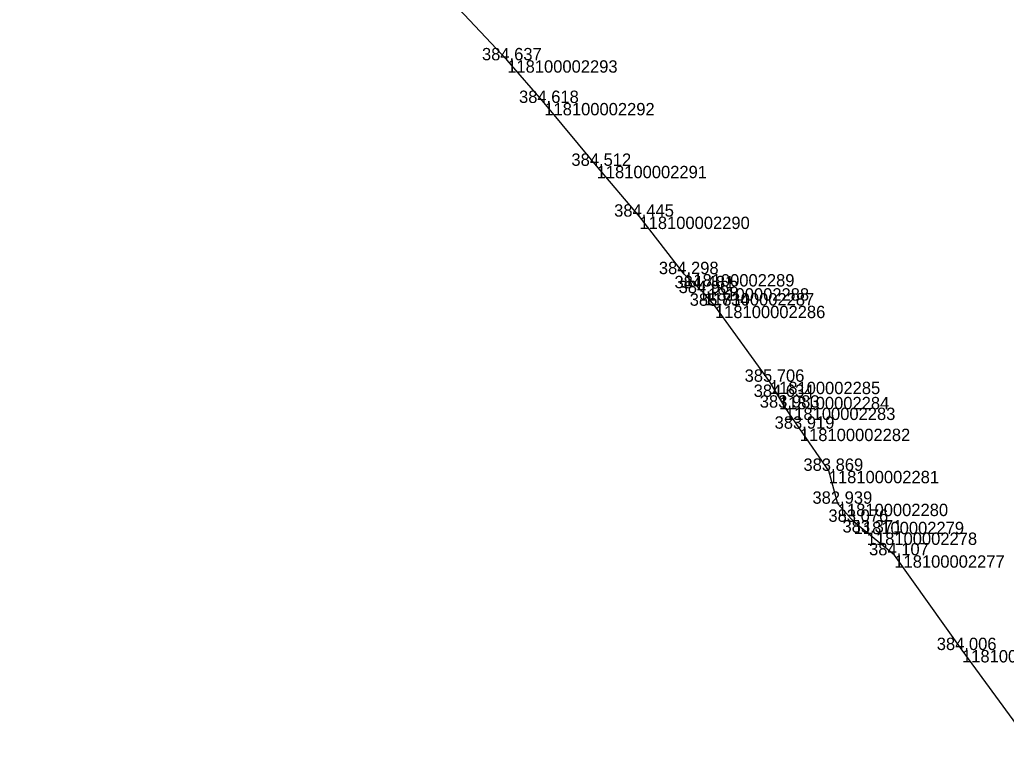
# Model space of a CAD drawing. Extents: x -724084 to -720954, y -948423 to -945131.
# Drawn here: x -721513.9 to -721418.2, y -948012.4 to -947941.8 of the extents above; entities that cross this region are included whole.
import ezdxf

# ---------------------------------------------------------------- set-up
doc = ezdxf.new("R2010")
doc.units = 0
for name, color, linetype in [('Vrstva 28', 7, 'Continuous'), ('Vrstva 31', 7, 'Continuous'), ('Vrstva 33', 7, 'Continuous'), ('Vrstva 60', 7, 'Continuous'), ('Vrstva 61', 7, 'Continuous')]:
    doc.layers.add(name, color=color, linetype=linetype)

msp = doc.modelspace()

# ---------------------------------------------------------------- linework, layer by layer
at = {"layer": 'Vrstva 28'}
for points in [[(-721448.033, -947967.826), (-721449.454, -947966.459), (-721453.791, -947960.883), (-721457.946, -947955.954), (-721463.023, -947949.853), (-721466.622, -947945.714), (-721471.841, -947940.171), (-721476.024, -947936.004), (-721481.396, -947930.254), (-721486.364, -947925.652), (-721492.33, -947920.175), (-721498.065, -947914.804), (-721503.374, -947910.249), (-721507.766, -947906.168), (-721509.45, -947905.616), (-721512.086, -947903.222), (-721513.94, -947901.829)], [(-721439.659, -947979.413), (-721440.252, -947978.369), (-721441.131, -947976.901), (-721446.462, -947969.527), (-721447.536, -947968.302), (-721448.033, -947967.826)], [(-721415.562, -948012.362), (-721422.481, -948002.931), (-721429.051, -947993.74), (-721431.726, -947991.529), (-721432.996, -947990.487), (-721434.542, -947988.736), (-721435.418, -947985.544), (-721438.218, -947981.456), (-721439.659, -947979.413)]]:
    msp.add_lwpolyline(points, dxfattribs=at)
at = {"layer": 'Vrstva 31'}
for points in [[(-721448.033, -947967.826), (-721449.454, -947966.459), (-721453.791, -947960.883), (-721457.946, -947955.954), (-721463.023, -947949.853), (-721466.622, -947945.714), (-721471.841, -947940.171), (-721476.024, -947936.004), (-721481.396, -947930.254), (-721486.364, -947925.652), (-721492.33, -947920.175), (-721498.065, -947914.804), (-721503.374, -947910.249), (-721507.766, -947906.168), (-721509.45, -947905.616), (-721512.086, -947903.222), (-721513.94, -947901.829)], [(-721439.659, -947979.413), (-721440.252, -947978.369), (-721441.131, -947976.901), (-721446.462, -947969.527), (-721447.536, -947968.302), (-721448.033, -947967.826)], [(-721415.562, -948012.362), (-721422.481, -948002.931), (-721429.051, -947993.74), (-721431.726, -947991.529), (-721432.996, -947990.487), (-721434.542, -947988.736), (-721435.418, -947985.544), (-721438.218, -947981.456), (-721439.659, -947979.413)]]:
    msp.add_lwpolyline(points, dxfattribs=at)
at = {"layer": 'Vrstva 33'}
msp.add_lwpolyline([(-721415.562, -948012.362), (-721422.481, -948002.931), (-721429.051, -947993.74), (-721431.726, -947991.529), (-721432.996, -947990.487), (-721434.542, -947988.736), (-721435.418, -947985.544), (-721438.218, -947981.456), (-721439.659, -947979.413), (-721440.252, -947978.369), (-721441.131, -947976.901), (-721446.462, -947969.527), (-721447.536, -947968.302), (-721448.033, -947967.826), (-721449.454, -947966.459), (-721453.791, -947960.883), (-721457.946, -947955.954), (-721463.023, -947949.853), (-721466.622, -947945.714), (-721471.841, -947940.171)], dxfattribs=at)
at = {"layer": 'Vrstva 60'}
for p, q in [((-721466.622, -947945.714), (-721466.622, -947945.714)), ((-721463.023, -947949.853), (-721463.023, -947949.853)), ((-721457.946, -947955.954), (-721457.946, -947955.954)), ((-721453.791, -947960.883), (-721453.791, -947960.883)), ((-721449.454, -947966.459), (-721449.454, -947966.459)), ((-721448.033, -947967.826), (-721448.033, -947967.826)), ((-721447.536, -947968.302), (-721447.536, -947968.302)), ((-721446.462, -947969.527), (-721446.462, -947969.527)), ((-721441.131, -947976.901), (-721441.131, -947976.901)), ((-721440.252, -947978.369), (-721440.252, -947978.369)), ((-721439.659, -947979.413), (-721439.659, -947979.413)), ((-721438.218, -947981.456), (-721438.218, -947981.456)), ((-721435.418, -947985.544), (-721435.418, -947985.544)), ((-721434.542, -947988.736), (-721434.542, -947988.736)), ((-721432.996, -947990.487), (-721432.996, -947990.487)), ((-721431.726, -947991.529), (-721431.726, -947991.529)), ((-721429.051, -947993.74), (-721429.051, -947993.74)), ((-721422.481, -948002.931), (-721422.481, -948002.931))]:
    msp.add_line(p, q, dxfattribs=at)

# ---------------------------------------------------------------- texts
for s, p in [('118100002293', (-721466.622, -947946.914)), ('118100002292', (-721463.023, -947951.053)), ('118100002291', (-721457.946, -947957.154)), ('118100002290', (-721453.791, -947962.083)), ('118100002289', (-721449.454, -947967.659)), ('118100002288', (-721448.033, -947969.026)), ('118100002287', (-721447.536, -947969.502)), ('118100002286', (-721446.462, -947970.727)), ('118100002285', (-721441.131, -947978.101)), ('118100002284', (-721440.252, -947979.569)), ('118100002283', (-721439.659, -947980.613)), ('118100002282', (-721438.218, -947982.656)), ('118100002281', (-721435.418, -947986.744)), ('118100002280', (-721434.542, -947989.936)), ('118100002279', (-721432.996, -947991.687)), ('118100002278', (-721431.726, -947992.729)), ('118100002277', (-721429.051, -947994.94)), ('118100002276', (-721422.481, -948004.131))]:
    msp.add_text(s, height=1.2, dxfattribs=at).set_placement(p)
at = {"layer": 'Vrstva 61'}
for s, p in [('384.637', (-721469.074, -947945.714)), ('384.618', (-721465.477, -947949.853)), ('384.512', (-721460.394, -947955.954)), ('384.445', (-721456.247, -947960.883)), ('384.298', (-721451.908, -947966.459)), ('384.481', (-721450.39, -947967.826)), ('384.963', (-721449.988, -947968.302)), ('385.734', (-721448.913, -947969.527)), ('385.706', (-721443.583, -947976.901)), ('384.634', (-721442.703, -947978.369)), ('383.983', (-721442.111, -947979.413)), ('383.919', (-721440.672, -947981.456)), ('383.869', (-721437.872, -947985.544)), ('382.939', (-721436.996, -947988.736)), ('383.076', (-721435.448, -947990.487)), ('383.371', (-721434.083, -947991.529)), ('384.107', (-721431.503, -947993.74)), ('384.006', (-721424.933, -948002.931))]:
    msp.add_text(s, height=1.2, dxfattribs=at).set_placement(p)

doc.saveas('drawing.dxf')
